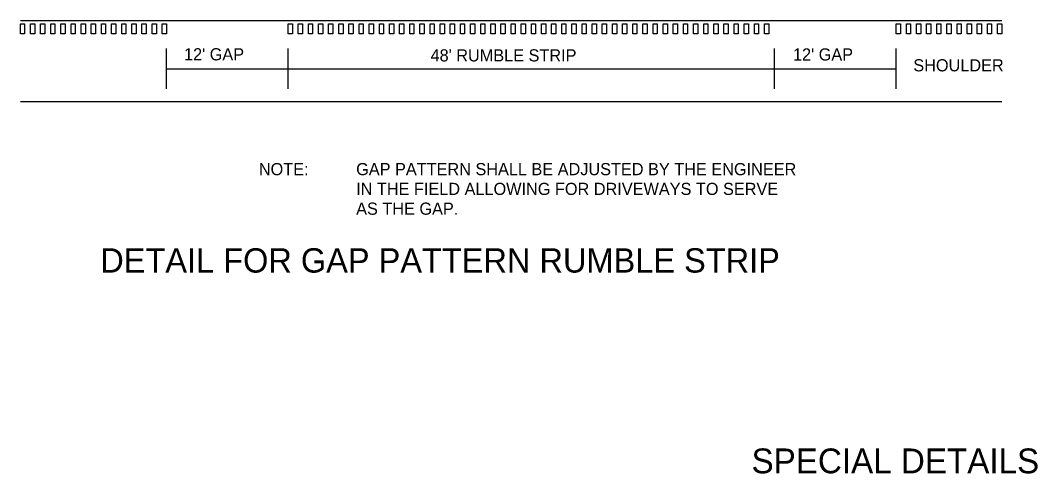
# Model space of a CAD drawing. Extents: x 1929624 to 1936506, y 596315 to 605721.
# Drawn here: x 1934812 to 1935314, y 600819 to 601042 of the extents above; entities that cross this region are included whole.
import ezdxf

# ---------------------------------------------------------------- set-up
doc = ezdxf.new("R2010")
doc.units = 0
doc.layers.add('R_Draft', color=7, linetype='Continuous')

msp = doc.modelspace()

# ---------------------------------------------------------------- linework, layer by layer
at = {"layer": 'R_Draft'}
for p, q in [((1934811.7, 601042.28), (1935295.86, 601042.28)), ((1934883.79, 601008.41), (1934883.79, 601028.41)), ((1934943.78, 601008.41), (1934943.78, 601028.41)), ((1935183.78, 601008.41), (1935183.78, 601028.41)), ((1935243.78, 601008.41), (1935243.78, 601028.41)), ((1934883.79, 601018.41), (1934943.78, 601018.41)), ((1934943.78, 601018.41), (1935183.78, 601018.41)), ((1935183.78, 601018.41), (1935243.78, 601018.41)), ((1934811.7, 601002.28), (1935295.86, 601002.28))]:
    msp.add_line(p, q, dxfattribs=at)
for points in [[(1934811.7, 601035.61), (1934811.7, 601040.61), (1934813.79, 601040.61), (1934813.79, 601035.61), (1934811.7, 601035.61)], [(1934816.7, 601035.61), (1934816.7, 601040.61), (1934818.79, 601040.61), (1934818.79, 601035.61), (1934816.7, 601035.61)], [(1934821.7, 601035.61), (1934821.7, 601040.61), (1934823.79, 601040.61), (1934823.79, 601035.61), (1934821.7, 601035.61)], [(1934826.7, 601035.61), (1934826.7, 601040.61), (1934828.79, 601040.61), (1934828.79, 601035.61), (1934826.7, 601035.61)], [(1934831.7, 601035.61), (1934831.7, 601040.61), (1934833.79, 601040.61), (1934833.79, 601035.61), (1934831.7, 601035.61)], [(1934836.7, 601035.61), (1934836.7, 601040.61), (1934838.79, 601040.61), (1934838.79, 601035.61), (1934836.7, 601035.61)], [(1934841.7, 601035.61), (1934841.7, 601040.61), (1934843.79, 601040.61), (1934843.79, 601035.61), (1934841.7, 601035.61)], [(1934846.7, 601035.61), (1934846.7, 601040.61), (1934848.79, 601040.61), (1934848.79, 601035.61), (1934846.7, 601035.61)], [(1934851.7, 601035.61), (1934851.7, 601040.61), (1934853.79, 601040.61), (1934853.79, 601035.61), (1934851.7, 601035.61)], [(1934856.7, 601035.61), (1934856.7, 601040.61), (1934858.79, 601040.61), (1934858.79, 601035.61), (1934856.7, 601035.61)], [(1934861.7, 601035.61), (1934861.7, 601040.61), (1934863.79, 601040.61), (1934863.79, 601035.61), (1934861.7, 601035.61)], [(1934866.7, 601035.61), (1934866.7, 601040.61), (1934868.79, 601040.61), (1934868.79, 601035.61), (1934866.7, 601035.61)], [(1934871.7, 601035.61), (1934871.7, 601040.61), (1934873.79, 601040.61), (1934873.79, 601035.61), (1934871.7, 601035.61)], [(1934876.7, 601035.61), (1934876.7, 601040.61), (1934878.79, 601040.61), (1934878.79, 601035.61), (1934876.7, 601035.61)], [(1934881.7, 601035.61), (1934881.7, 601040.61), (1934883.79, 601040.61), (1934883.79, 601035.61), (1934881.7, 601035.61)], [(1934943.8, 601035.61), (1934943.8, 601040.61), (1934945.88, 601040.61), (1934945.88, 601035.61), (1934943.8, 601035.61)], [(1934948.8, 601035.61), (1934948.8, 601040.61), (1934950.88, 601040.61), (1934950.88, 601035.61), (1934948.8, 601035.61)], [(1934953.8, 601035.61), (1934953.8, 601040.61), (1934955.88, 601040.61), (1934955.88, 601035.61), (1934953.8, 601035.61)], [(1934958.8, 601035.61), (1934958.8, 601040.61), (1934960.88, 601040.61), (1934960.88, 601035.61), (1934958.8, 601035.61)], [(1934963.8, 601035.61), (1934963.8, 601040.61), (1934965.88, 601040.61), (1934965.88, 601035.61), (1934963.8, 601035.61)], [(1934968.8, 601035.61), (1934968.8, 601040.61), (1934970.88, 601040.61), (1934970.88, 601035.61), (1934968.8, 601035.61)], [(1934973.8, 601035.61), (1934973.8, 601040.61), (1934975.88, 601040.61), (1934975.88, 601035.61), (1934973.8, 601035.61)], [(1934978.8, 601035.61), (1934978.8, 601040.61), (1934980.88, 601040.61), (1934980.88, 601035.61), (1934978.8, 601035.61)], [(1934983.8, 601035.61), (1934983.8, 601040.61), (1934985.88, 601040.61), (1934985.88, 601035.61), (1934983.8, 601035.61)], [(1934988.8, 601035.61), (1934988.8, 601040.61), (1934990.88, 601040.61), (1934990.88, 601035.61), (1934988.8, 601035.61)], [(1934993.8, 601035.61), (1934993.8, 601040.61), (1934995.88, 601040.61), (1934995.88, 601035.61), (1934993.8, 601035.61)], [(1934998.8, 601035.61), (1934998.8, 601040.61), (1935000.88, 601040.61), (1935000.88, 601035.61), (1934998.8, 601035.61)], [(1935003.8, 601035.61), (1935003.8, 601040.61), (1935005.88, 601040.61), (1935005.88, 601035.61), (1935003.8, 601035.61)], [(1935008.8, 601035.61), (1935008.8, 601040.61), (1935010.88, 601040.61), (1935010.88, 601035.61), (1935008.8, 601035.61)], [(1935013.8, 601035.61), (1935013.8, 601040.61), (1935015.88, 601040.61), (1935015.88, 601035.61), (1935013.8, 601035.61)], [(1935018.8, 601035.61), (1935018.8, 601040.61), (1935020.88, 601040.61), (1935020.88, 601035.61), (1935018.8, 601035.61)], [(1935023.8, 601035.61), (1935023.8, 601040.61), (1935025.88, 601040.61), (1935025.88, 601035.61), (1935023.8, 601035.61)], [(1935028.8, 601035.61), (1935028.8, 601040.61), (1935030.88, 601040.61), (1935030.88, 601035.61), (1935028.8, 601035.61)], [(1935033.8, 601035.61), (1935033.8, 601040.61), (1935035.88, 601040.61), (1935035.88, 601035.61), (1935033.8, 601035.61)], [(1935038.8, 601035.61), (1935038.8, 601040.61), (1935040.88, 601040.61), (1935040.88, 601035.61), (1935038.8, 601035.61)], [(1935043.8, 601035.61), (1935043.8, 601040.61), (1935045.88, 601040.61), (1935045.88, 601035.61), (1935043.8, 601035.61)], [(1935048.8, 601035.61), (1935048.8, 601040.61), (1935050.88, 601040.61), (1935050.88, 601035.61), (1935048.8, 601035.61)], [(1935053.8, 601035.61), (1935053.8, 601040.61), (1935055.88, 601040.61), (1935055.88, 601035.61), (1935053.8, 601035.61)], [(1935058.8, 601035.61), (1935058.8, 601040.61), (1935060.88, 601040.61), (1935060.88, 601035.61), (1935058.8, 601035.61)], [(1935063.8, 601035.61), (1935063.8, 601040.61), (1935065.88, 601040.61), (1935065.88, 601035.61), (1935063.8, 601035.61)], [(1935068.8, 601035.61), (1935068.8, 601040.61), (1935070.88, 601040.61), (1935070.88, 601035.61), (1935068.8, 601035.61)], [(1935073.8, 601035.61), (1935073.8, 601040.61), (1935075.88, 601040.61), (1935075.88, 601035.61), (1935073.8, 601035.61)], [(1935078.8, 601035.61), (1935078.8, 601040.61), (1935080.88, 601040.61), (1935080.88, 601035.61), (1935078.8, 601035.61)], [(1935083.8, 601035.61), (1935083.8, 601040.61), (1935085.88, 601040.61), (1935085.88, 601035.61), (1935083.8, 601035.61)], [(1935088.8, 601035.61), (1935088.8, 601040.61), (1935090.88, 601040.61), (1935090.88, 601035.61), (1935088.8, 601035.61)], [(1935093.8, 601035.61), (1935093.8, 601040.61), (1935095.88, 601040.61), (1935095.88, 601035.61), (1935093.8, 601035.61)], [(1935098.8, 601035.61), (1935098.8, 601040.61), (1935100.88, 601040.61), (1935100.88, 601035.61), (1935098.8, 601035.61)], [(1935103.8, 601035.61), (1935103.8, 601040.61), (1935105.88, 601040.61), (1935105.88, 601035.61), (1935103.8, 601035.61)], [(1935108.8, 601035.61), (1935108.8, 601040.61), (1935110.88, 601040.61), (1935110.88, 601035.61), (1935108.8, 601035.61)], [(1935113.8, 601035.61), (1935113.8, 601040.61), (1935115.88, 601040.61), (1935115.88, 601035.61), (1935113.8, 601035.61)], [(1935118.8, 601035.61), (1935118.8, 601040.61), (1935120.88, 601040.61), (1935120.88, 601035.61), (1935118.8, 601035.61)], [(1935123.8, 601035.61), (1935123.8, 601040.61), (1935125.88, 601040.61), (1935125.88, 601035.61), (1935123.8, 601035.61)], [(1935128.8, 601035.61), (1935128.8, 601040.61), (1935130.88, 601040.61), (1935130.88, 601035.61), (1935128.8, 601035.61)], [(1935133.8, 601035.61), (1935133.8, 601040.61), (1935135.88, 601040.61), (1935135.88, 601035.61), (1935133.8, 601035.61)], [(1935138.8, 601035.61), (1935138.8, 601040.61), (1935140.88, 601040.61), (1935140.88, 601035.61), (1935138.8, 601035.61)], [(1935143.8, 601035.61), (1935143.8, 601040.61), (1935145.88, 601040.61), (1935145.88, 601035.61), (1935143.8, 601035.61)], [(1935148.8, 601035.61), (1935148.8, 601040.61), (1935150.88, 601040.61), (1935150.88, 601035.61), (1935148.8, 601035.61)], [(1935153.8, 601035.61), (1935153.8, 601040.61), (1935155.88, 601040.61), (1935155.88, 601035.61), (1935153.8, 601035.61)], [(1935158.8, 601035.61), (1935158.8, 601040.61), (1935160.88, 601040.61), (1935160.88, 601035.61), (1935158.8, 601035.61)], [(1935163.8, 601035.61), (1935163.8, 601040.61), (1935165.88, 601040.61), (1935165.88, 601035.61), (1935163.8, 601035.61)], [(1935168.8, 601035.61), (1935168.8, 601040.61), (1935170.88, 601040.61), (1935170.88, 601035.61), (1935168.8, 601035.61)], [(1935173.8, 601035.61), (1935173.8, 601040.61), (1935175.88, 601040.61), (1935175.88, 601035.61), (1935173.8, 601035.61)], [(1935178.8, 601035.61), (1935178.8, 601040.61), (1935180.88, 601040.61), (1935180.88, 601035.61), (1935178.8, 601035.61)], [(1935243.78, 601035.61), (1935243.78, 601040.61), (1935245.86, 601040.61), (1935245.86, 601035.61), (1935243.78, 601035.61)], [(1935248.78, 601035.61), (1935248.78, 601040.61), (1935250.86, 601040.61), (1935250.86, 601035.61), (1935248.78, 601035.61)], [(1935253.78, 601035.61), (1935253.78, 601040.61), (1935255.86, 601040.61), (1935255.86, 601035.61), (1935253.78, 601035.61)], [(1935258.78, 601035.61), (1935258.78, 601040.61), (1935260.86, 601040.61), (1935260.86, 601035.61), (1935258.78, 601035.61)], [(1935263.78, 601035.61), (1935263.78, 601040.61), (1935265.86, 601040.61), (1935265.86, 601035.61), (1935263.78, 601035.61)], [(1935268.78, 601035.61), (1935268.78, 601040.61), (1935270.86, 601040.61), (1935270.86, 601035.61), (1935268.78, 601035.61)], [(1935273.78, 601035.61), (1935273.78, 601040.61), (1935275.86, 601040.61), (1935275.86, 601035.61), (1935273.78, 601035.61)], [(1935278.78, 601035.61), (1935278.78, 601040.61), (1935280.86, 601040.61), (1935280.86, 601035.61), (1935278.78, 601035.61)], [(1935283.78, 601035.61), (1935283.78, 601040.61), (1935285.86, 601040.61), (1935285.86, 601035.61), (1935283.78, 601035.61)], [(1935288.78, 601035.61), (1935288.78, 601040.61), (1935290.86, 601040.61), (1935290.86, 601035.61), (1935288.78, 601035.61)], [(1935293.78, 601035.61), (1935293.78, 601040.61), (1935295.86, 601040.61), (1935295.86, 601035.61), (1935293.78, 601035.61)]]:
    msp.add_lwpolyline(points, dxfattribs=at)

# ---------------------------------------------------------------- texts
for s, height, p in [("12' GAP", 6, (1934892.44, 601022.53)), ("48' RUMBLE STRIP", 5.9999, (1935014.06, 601022)), ("12' GAP", 6, (1935192.85, 601022.46)), ('SHOULDER', 6, (1935252.22, 601017.11)), ('NOTE:', 6, (1934929.36, 600965.88)), ('GAP PATTERN SHALL BE ADJUSTED BY THE ENGINEER', 5.9999, (1934977.36, 600965.88)), ('IN THE FIELD ALLOWING FOR DRIVEWAYS TO SERVE', 5.9999, (1934977.36, 600956.13)), ('AS THE GAP.', 5.9999, (1934977.36, 600946.38)), ('DETAIL FOR GAP PATTERN RUMBLE STRIP', 11.9997, (1934851.14, 600917.84)), ('SPECIAL DETAILS', 12.2397, (1935172.4, 600818.82))]:
    msp.add_text(s, height=height, dxfattribs=at).set_placement(p)

doc.saveas('drawing.dxf')
